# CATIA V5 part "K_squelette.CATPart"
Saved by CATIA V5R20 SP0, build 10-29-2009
Part number: squelette
Publications: "R cardan", "R palier", "Sommet", "Sommet1", "Sommet2", "Sommet3", "debut", "interface 11/V", "debut 16", "Esquisse.6", "Nb dents", "diamètre ext cardanr", "axe general", "Origine", "Sommet4", "Sommet5", "Sommet6", "hauteur du visco", "R interne", "interface visco/embrayage", "Rint embrayage", "R interface stat_tot", "stator_rotor1", "stator_rotor2", "stator_rotor3", "D axe", "Axe 2", "Axe 1", "Zs", "Zp", "Sommet7", "Sommet8", "Sommet9", "Sommet10", "Sommet11", "Sommet12", "Lmeplat", "Rmeplat", "R appui", "Lappui", "disques/V", "Module"
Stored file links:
  G:\Khaled_CFAO_2011\ST2M\ST2M_GR1\mponsin\Khaled\CAD_ThinkMOTION\K_squelette.CATPart
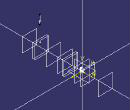
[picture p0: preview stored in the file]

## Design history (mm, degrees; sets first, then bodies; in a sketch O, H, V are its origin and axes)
Parameters
  `R cardan` = 30 mm
  `R palier` = 70 mm
  Zp = 60
  Zs = 30
  Module = 4 mm
Body1 (main body)
  Point1 "Origine": (0, 0, 0)
  Line1 "axe general": type Normal, RefPoint Point1, RefSkin zx-plane, Start -43, End 70
  Set1 "Coquille 16"
    Plane1 "debut 16": type Offset, RefPlane zx-plane, Offset -450 {= `Set1.d(debut16,O)`}
    Plane2 "interface 16/visco": type Offset, RefPlane Plane1, Offset 90 {= `Set1.Longueur interne 16`}
    Sketch1 "Interface 16/11" on yz-plane, origin (0, 0, 0), H (0, 1, 0), V (0, 0, 1)
      line L1 (-358, 239.8651) -> (-358, 189.8651)
      line L2 (-358, 189.8651) -> (-363, 189.8651)
      line L3 (-363, 189.8651) -> (-363, 165)
      point P4 (-363, 165)
      reference intersected line E1 through (-360, 0) direction (0, 1) from Plane2
      reference projected line E2 through (0, 0) direction (1, 0) from Line1
      length L2 = 5 {= `Set1.Longueur centrage`}
      length L1 = 50 {= `Set1.hauteur appui plan`}
      distance L3 E1 = 3 {= `Set1.distance visco/11`}
      distance P4 E2 = 165 {= `Set1.rayon interne 11`}
      vertical: L1 V, L3 V
      horizontal: L2 H
  Set2 "Coquille 11"
    Plane3 "debut": type Offset, RefPlane zx-plane, Offset 200
    Plane4 "interface 11/V": type Offset, RefPlane zx-plane, Offset 50
  Set3 "viscocoupleur"
    Plane5 "interface visco/embrayage": type Offset, RefPlane zx-plane, Offset -110
    Sketch2 "interface visco/16" on yz-plane, origin (0, 0, 0), H (0, 1, 0), V (0, 0, 1)
      line L1 (-360, 43) -> (-360, 33)
      line L2 (-360, 33) -> (-364, 33)
      reference projected line E1 through (0, 0) direction (1, 0) from Line1
      reference intersected line E2 through (-360, 0) direction (0, 1) from Plane2
      distance L2 E1 = 33 {= 3mm+`Set4.diamètre ext cardanr` /2}
      length L2 = 4 {= `Set3.Longueur guidage`}
      length L1 = 10 {= `Set3.hauteur guidage`}
      vertical: L1 V
      horizontal: L2 H
      coincidence: E2 L1
    Plane6 "stator_rotor1": type Offset, RefPlane Plane2, Offset 15
    Plane7 "stator_rotor2": type Offset, RefPlane Plane6, Offset 100
    Plane8 "stator_rotor3": type Offset, RefPlane Plane7, Offset 100
  Set4 "cannelure cardan"
    Sketch3 on zx-plane, origin (0, 0, 0), H (-1, 0, 0), V (0, 0, 1)
      arc A1 centre (0, 0) radius 30 from (0, 30) to (-7.7646, 28.9778) ccw
      arc A2 centre (0, 0) radius 25 from (-6.4705, 24.1481) to (-12.5, 21.6506) ccw
      construction line L1 (0, 0) -> (-64.9386, 112.477)
      construction line L2 (0, 0) -> (-12.941, 48.2963)
      point P2 (0, 0)
      axis line L3 (0, 0) -> (0, 121.0477)
      point P5 (-15, 25.9808)
      line L4 (-6.4705, 24.1481) -> (-7.7646, 28.9778)
      point P6 (-6.4705, 24.1481)
      point P7 (-7.7646, 28.9778)
      point P8 (0, 30)
      point P9 (-7.7646, 28.9778)
      point P10 (-6.4705, 24.1481)
      point P11 (-12.5, 21.6506)
      line L5 (-12.5, 21.6506) -> (0, 0)
      line L6 (0, 30) -> (0, 0)
      point P12 (0, 30)
      reference projected point E1 (0, 0) from Point1
      distance A2 A1 = 5 {= `Set4.hauteur de dent`}
      distance P8 E1 = 30 {= `Set4.diamètre ext cardanr` /2}
      angle L1 L3 = 30 {= 360deg /`Set4.Nb dents`}
      coincidence: P2 L1, P2 V, P5 A1, P5 L1, P7 A1, L3 P8, L2 P9, L2 P10, L1 P11, P6 P10, P12 A1, P7 P9, P8 P12
      midpoint: P6 L2
      parallelism: L4 L2, L5 L1
      symmetry: L1 L3 L2
      vertical: L3 V, L6 V
  Set5 "axe"
    Line2 "Axe 2": type Normal, RefPoint Point1, RefSkin xy-plane, Start -43, End 70
    Line3 "Axe 1": type Normal, RefPoint Point1, RefSkin yz-plane, Start -43, End 70
    Sketch4 on xy-plane, origin (0, 0, 0), H (1, 0, 0), V (0, 1, 0)
      line L1 (-5, 7.5) -> (-5, -7.5)
      point P1 (-5, 7.5)
      line L2 (5, 7.5) -> (5, -7.5)
      point P4 (5, -7.5)
      reference projected line E1 through (0, 0) direction (0, 1) from Line1
      arc A1 centre (0, -7.5) radius 5 from (-5, -7.5) to (5, -7.5) ccw
      point P5 (0, -7.5)
      point P6 (5, -7.5)
      arc A2 centre (0, 7.5) radius 5 from (5, 7.5) to (-5, 7.5) ccw
      point P7 (0, 7.5)
      point P8 (-5, 7.5)
      construction line L3 (5, -7.5) -> (0, -7.5)
      axis line L4 (-5, 7.5) -> (0, 7.5)
      point P9 (0, 7.5)
      point P10 (0, -7.5)
      radius A1 = 5 {= Set5.Rmeplat}
      distance A2 A1 = 25 {= Set5.Lmeplat}
      vertical: L1 V, L2 V
      symmetry: L1 L2 E1, L3 L4 H
      coincidence: P5 V, P7 V, P8 L1, P6 P4, P1 P8, P9 P7, P10 P5
      tangency: A1 L1, A2 L1
      horizontal: L3 H, L4 H
  Set6 "embrayage"
    Plane9 "disques/V": type Offset, RefPlane Plane5, Offset 15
